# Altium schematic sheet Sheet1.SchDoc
size A4
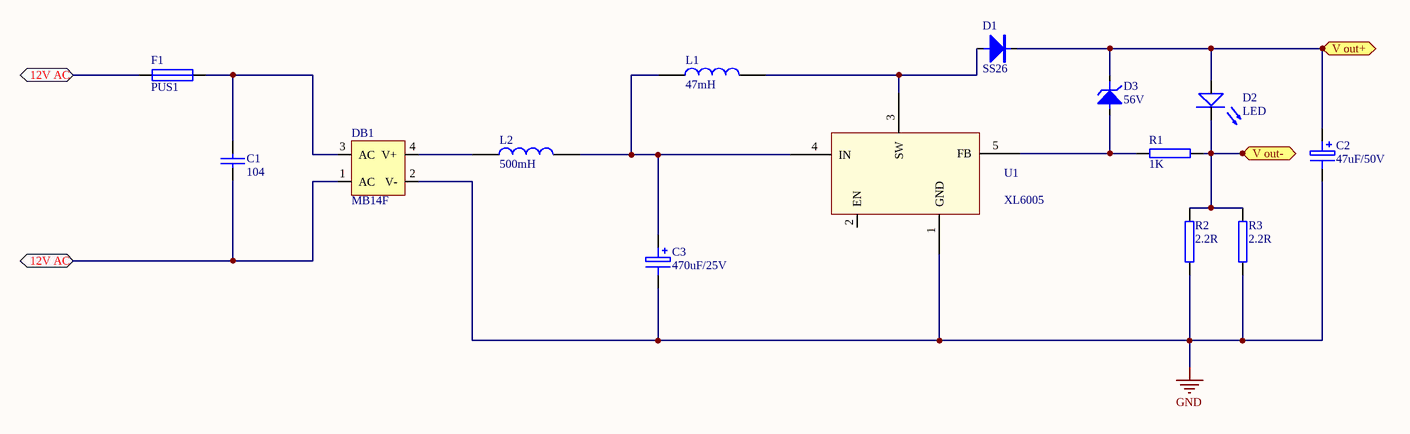
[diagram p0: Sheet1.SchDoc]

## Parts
C1  104  [0805]
C2  47uF/50V  [CE-V10*20]
C3  470uF/25V  [CE-V10*20]
D1  SS26  [DO-214]
D2  LED
D3  56V  [LL34]
DB1  MB14F  [SDIP-4]
F1  PUS1  [F-H3.6*10]
L1  47mH
L2  500mH
R1  1K  [1206]
R2  2.2R  [1206]
R3  2.2R  [1206]
U1  XL6005

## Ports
12V AC, V out+, V out-

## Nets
GND: C2.2 C3.2 DB1.2(V-) R2.1 R3.1 U1.1(GND)
12V AC: C1.2 DB1.1(AC) F1.1 ; port 12V AC
V out+: C2.1 D1.2(K) D2.+ D3.2(K) ; port V out+
V out-: D2.- R1.2 R2.2 R3.2 ; port V out-
NetC1_1: C1.1 DB1.3(AC) F1.2
NetC3_1: C3.1 L1.1 L2.2 U1.4(IN)
NetD1_1: D1.1(A) L1.2 U1.3(SW)
NetD3_1: D3.1(A) R1.1 U1.5(FB)
NetDB1_4: DB1.4(V+) L2.1

Not connected (* = marked no-connect by the designer): U1 2(EN)

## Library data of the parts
C1 = 无极C: Capacitor
C2 C3 = 有极C: Electrolytic Capacitor
D1 = DIODE
D3 = 二极管: Zener Diode
DB1 = 整流桥: Diode Bridge
F1 = F1: Fuse
L1 L2 = L-1
R1-R3 = 电阻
